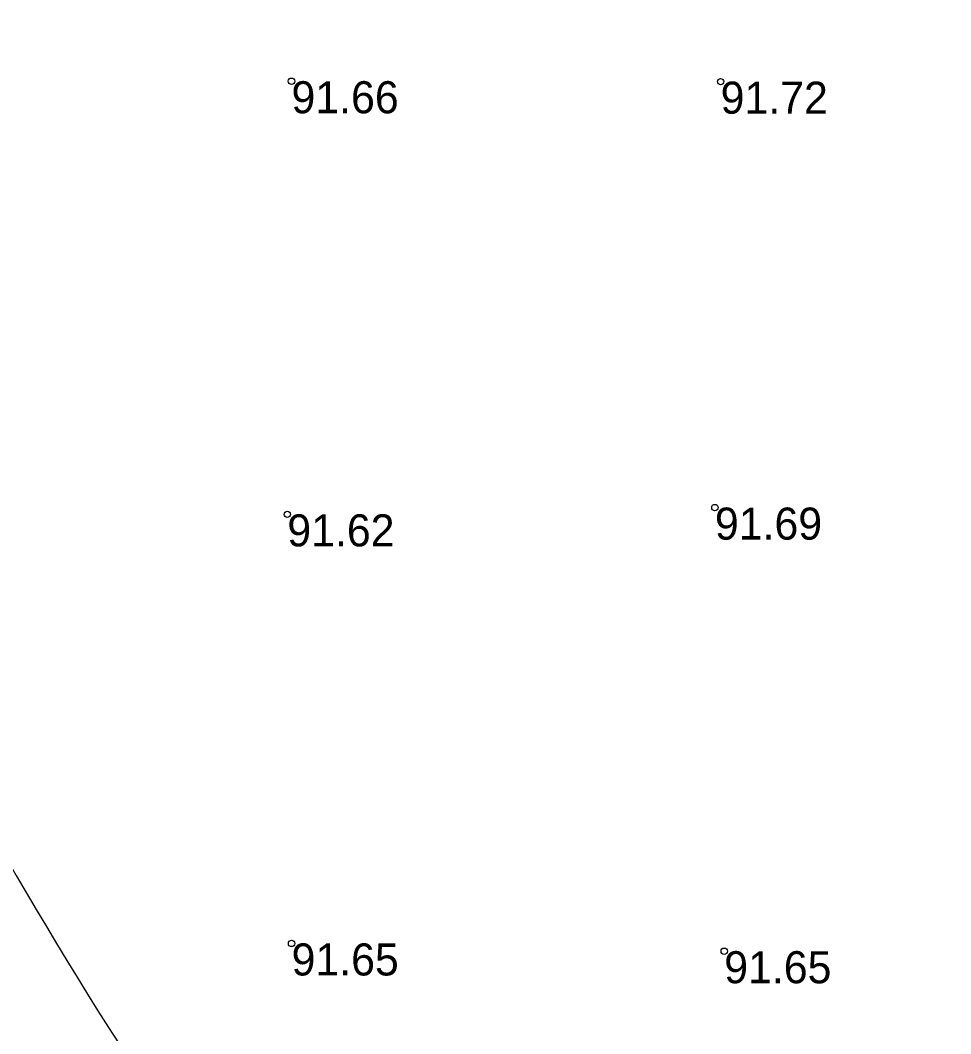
# Model space of a CAD drawing. Extents: x 316000 to 728450, y 314368 to 726000.
# Drawn here: x 726108.1 to 726217, y 315253.8 to 315372.4 of the extents above; entities that cross this region are included whole.
import ezdxf

# ---------------------------------------------------------------- set-up
doc = ezdxf.new("R2010")
doc.units = 0
for name, color, linetype in [('RELJ_AATZ_####_TKST_#', 7, 'Continuous'), ('RELJ_ELEM_####_####_#', 7, 'Continuous'), ('RELJ_HORZ_PAMT_####_#', 7, 'Continuous'), ('RELJ_NOGA_####_####_#', 7, 'Continuous')]:
    doc.layers.add(name, color=color, linetype=linetype)

msp = doc.modelspace()

# ---------------------------------------------------------------- linework, layer by layer
at = {"layer": 'RELJ_ELEM_####_####_#'}
for centre in [(726139.82, 315365.27), (726190.06, 315365.22), (726189.39, 315315.37), (726139.33, 315314.58), (726139.83, 315264.36), (726190.48, 315263.45)]:
    msp.add_circle(centre, 0.375, dxfattribs=at)
at = {"layer": 'RELJ_HORZ_PAMT_####_#'}
msp.add_spline([(726116.34, 315699.09), (726105.94, 315702.69), (726040.13, 315715), (725990.82, 315710.42), (725942.03, 315708.25), (725920.28, 315706.77), (725880.37, 315714.51), (725859.05, 315708.68), (725859.05, 315672.66), (725851.26, 315613.97), (725853.47, 315568.9), (725841, 315555.79), (725885.56, 315509.63), (725935.94, 315461.49), (725983.42, 315406.25), (726032.86, 315360.51), (726082.85, 315311.19), (726122.23, 315248.76), (726137.05, 315229.29), (726180.19, 315183.1), (726194.52, 315168.27), (726211.91, 315146.93), (726212.51, 315143.16)], degree=3, dxfattribs=at)
at = {"layer": 'RELJ_NOGA_####_####_#'}
for points in [[(726259.12, 315084.51), (726262.72, 315089.26), (726261.56, 315090.84), (726260.2, 315092.42), (726257.29, 315095.53), (726218.91, 315136.38), (726180.31, 315176.84), (726128.67, 315229.97), (726063.7, 315298.11), (725999.9, 315366.09), (725937.21, 315432.09), (725876.35, 315495.23), (725810.58, 315563.08), (725744.7, 315632.91)], [(725740.86, 315626.98), (725805.54, 315558.12), (725870.39, 315491.15), (725932.8, 315426.8), (725994.98, 315360.84), (726059.66, 315292.12), (726075.75, 315275.46), (726092.08, 315259.04), (726108.47, 315242.67), (726124.69, 315226.14), (726193.27, 315154.03), (726250.06, 315092.6), (726256.32, 315085.83), (726258.82, 315084.29), (726259.12, 315084.51)]]:
    msp.add_spline(points, degree=3, dxfattribs=at)

# ---------------------------------------------------------------- texts
at = {"layer": 'RELJ_AATZ_####_TKST_#'}
for s, p in [('91.66', (726139.82, 315361.52)), ('91.72', (726190.06, 315361.47)), ('91.69', (726189.39, 315311.62)), ('91.62', (726139.33, 315310.83)), ('91.65', (726139.83, 315260.61)), ('91.65', (726190.48, 315259.7))]:
    msp.add_text(s, height=3.75, dxfattribs=at).set_placement(p)

doc.saveas('drawing.dxf')
